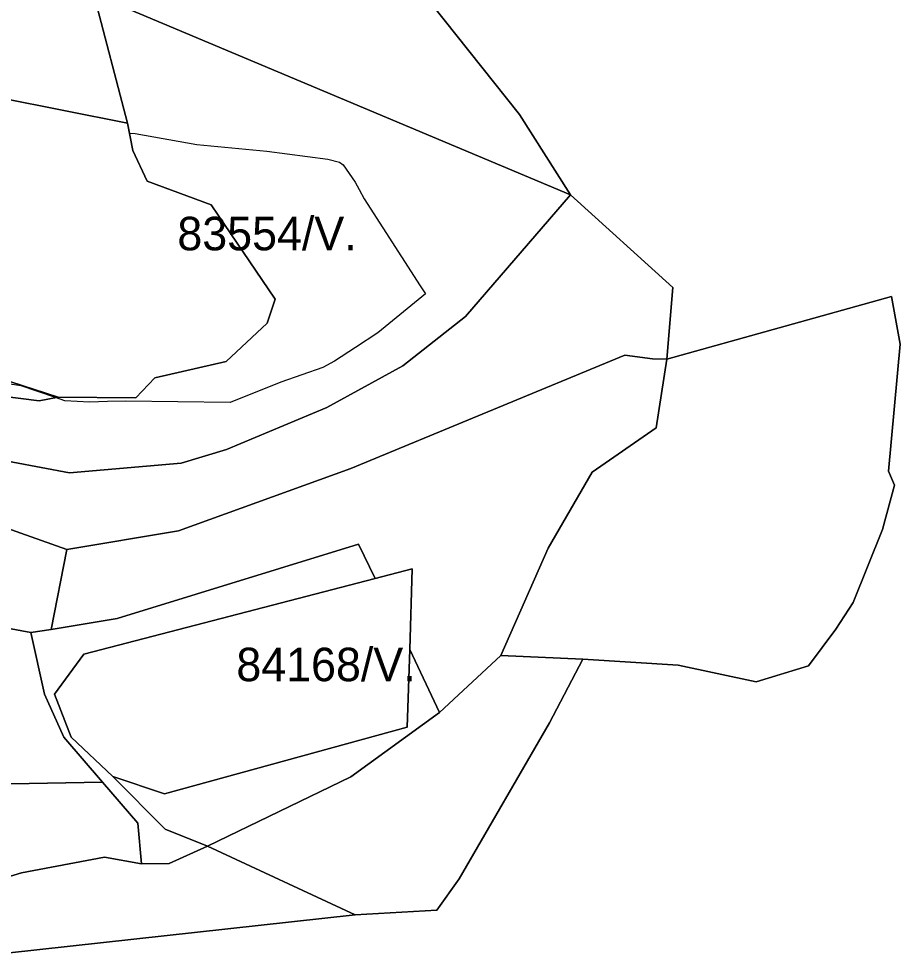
# Model space of a CAD drawing. Extents: x -477304 to -465429, y -1159113 to -1149210.
# Drawn here: x -473852.4 to -473457.6, y -1153159.5 to -1152741 of the extents above; entities that cross this region are included whole.
import ezdxf

# ---------------------------------------------------------------- set-up
doc = ezdxf.new("R2010")
doc.units = 0
for name, color, linetype in [('BPEJ_s', 7, 'Continuous'), ('PUPFL_s', 7, 'Continuous'), ('trav_porost_s', 7, 'Continuous')]:
    doc.layers.add(name, color=color, linetype=linetype)

msp = doc.modelspace()

# ---------------------------------------------------------------- linework, layer by layer
at = {"layer": 'BPEJ_s'}
for points in [[(-473860.68, -1152776.54), (-473803.74, -1152787.82), (-473802.88, -1152792.33), (-473800.3, -1152792.48), (-473772.63, -1152797.38), (-473760.04, -1152798.58), (-473741.35, -1152800.35), (-473713.91, -1152803.97), (-473708.8, -1152805.25), (-473707.1, -1152806.53), (-473701.78, -1152814.19), (-473700.01, -1152817.45), (-473697.73, -1152821.63), (-473672.63, -1152860.57), (-473670.24, -1152864.27), (-473691.56, -1152881.64), (-473701.53, -1152888.21), (-473710.93, -1152894.4), (-473716.25, -1152897.17), (-473734.97, -1152903.77), (-473757.74, -1152912.92), (-473804.55, -1152912.28), (-473812.67, -1152912.49), (-473820.72, -1152912.7), (-473831.78, -1152912.06), (-473835.95, -1152910.66), (-473851.36, -1152905.47), (-473856.47, -1152904.62)], [(-473860.68, -1152776.54), (-473803.74, -1152787.82), (-473802.88, -1152792.33), (-473800.3, -1152792.48), (-473772.63, -1152797.38), (-473760.04, -1152798.58), (-473741.35, -1152800.35), (-473713.91, -1152803.97), (-473708.8, -1152805.25), (-473707.1, -1152806.53), (-473701.78, -1152814.19), (-473700.01, -1152817.45), (-473697.73, -1152821.63), (-473672.63, -1152860.57), (-473670.24, -1152864.27), (-473691.56, -1152881.64), (-473701.53, -1152888.21), (-473710.93, -1152894.4), (-473716.25, -1152897.17), (-473734.97, -1152903.77), (-473757.74, -1152912.92), (-473804.55, -1152912.28), (-473812.67, -1152912.49), (-473820.72, -1152912.7), (-473831.78, -1152912.06), (-473835.95, -1152910.66), (-473851.36, -1152905.47), (-473856.47, -1152904.62)], [(-473677.19, -1153023.46), (-473678.51, -1153058.19), (-473787.15, -1153088.01), (-473810.27, -1153080.25), (-473828.87, -1153062.69), (-473836.45, -1153043.48), (-473823.31, -1153025.6), (-473692.78, -1152991.62), (-473676.17, -1152987.29), (-473677.19, -1153023.46)]]:
    msp.add_lwpolyline(points, dxfattribs=at)
msp.add_lwpolyline([(-473678.51, -1153058.19), (-473787.15, -1153088.01), (-473810.27, -1153080.25), (-473828.87, -1153062.69), (-473836.45, -1153043.48), (-473823.31, -1153025.6), (-473692.78, -1152991.62), (-473676.17, -1152987.29), (-473677.19, -1153023.46)], close=True, dxfattribs=at)
at = {"layer": 'PUPFL_s'}
for points in [[(-473869.86, -1152675.74), (-473854.44, -1152610.53), (-473844.11, -1152615.69), (-473806.25, -1152626.1), (-473785.42, -1152640.23), (-473773.81, -1152648.75), (-473720.65, -1152687.75), (-473718.59, -1152689.27), (-473689.18, -1152710.85), (-473681.31, -1152718.42), (-473667.69, -1152734.2), (-473628.1, -1152783.99), (-473605.28, -1152819.93), (-473818.76, -1152730.12), (-473866.02, -1152692.05)], [(-473605.28, -1152819.93), (-473559.4, -1152861.38), (-473562.2, -1152893.41), (-473568.51, -1152893.26), (-473580.94, -1152891.7), (-473703.65, -1152942.41), (-473780.92, -1152970.39), (-473830.88, -1152978.61), (-473858.21, -1152968.94), (-473932.87, -1152939.58), (-473931.31, -1152925.22), (-473829.65, -1152944.31), (-473779.71, -1152940.02), (-473759.33, -1152933.96), (-473714.49, -1152915.07), (-473680.41, -1152896.49), (-473652.27, -1152874.34)], [(-473636.51, -1153026.2), (-473615.22, -1152978.15), (-473595.64, -1152944.05), (-473566.85, -1152924.27), (-473562.2, -1152893.41), (-473461.58, -1152865.37), (-473457.56, -1152886.8), (-473462.87, -1152943.67), (-473460.13, -1152949.8), (-473465.6, -1152969.78), (-473478.61, -1153002.33), (-473486.49, -1153014.41), (-473498.71, -1153030.69), (-473522.18, -1153037.94), (-473557.06, -1153030.52), (-473599.81, -1153027.7)], [(-473843.32, -1152912.12), (-473875.09, -1152908.03), (-473902.48, -1152910.74), (-473948.56, -1152907.91), (-473962.68, -1152914.6), (-473964.53, -1152910.42), (-473951.84, -1152902.09), (-473947.37, -1152895.8), (-473928.69, -1152905.66), (-473922.23, -1152891.44), (-473904.07, -1152888.15), (-473834.72, -1152910.42)], [(-473663.99, -1153051.68), (-473677.19, -1153023.46), (-473676.17, -1152987.29), (-473692.78, -1152991.62), (-473700.17, -1152976.27), (-473808.35, -1153009.59), (-473837.96, -1153014.54), (-473830.88, -1152978.61), (-473780.92, -1152970.39), (-473703.65, -1152942.41), (-473580.94, -1152891.7), (-473568.51, -1152893.26), (-473562.2, -1152893.41), (-473566.85, -1152924.27), (-473595.64, -1152944.05), (-473615.22, -1152978.15), (-473636.51, -1153026.2)], [(-473941.25, -1152960.21), (-473960.61, -1152963.03), (-473932.87, -1152939.58), (-473858.21, -1152968.94), (-473830.88, -1152978.61), (-473837.96, -1153014.54), (-473846.96, -1153015.83), (-473896.11, -1153006.76), (-473901.36, -1153006.1), (-473923.74, -1152985.01)], [(-473810.27, -1153080.25), (-473786.86, -1153103.88), (-473767.89, -1153111.54), (-473785.09, -1153119.27), (-473797.46, -1153119.43), (-473799.07, -1153101.23), (-473814.86, -1153082.86), (-473832.18, -1153062.72), (-473840.86, -1153043.38), (-473846.96, -1153015.83), (-473837.96, -1153014.54), (-473808.35, -1153009.59), (-473700.17, -1152976.27), (-473692.78, -1152991.62), (-473823.31, -1153025.6), (-473836.45, -1153043.48), (-473828.87, -1153062.69)], [(-473917.16, -1153024.93), (-473896.11, -1153006.76), (-473846.96, -1153015.83), (-473840.86, -1153043.38), (-473832.18, -1153062.72), (-473814.86, -1153082.86), (-473921.91, -1153084.81), (-473923.67, -1153077.2), (-473937.86, -1153051.01)], [(-473677.19, -1153023.46), (-473663.99, -1153051.68), (-473703.72, -1153080.41), (-473767.89, -1153111.54), (-473786.86, -1153103.88), (-473810.27, -1153080.25), (-473787.15, -1153088.01), (-473678.51, -1153058.19)], [(-473636.51, -1153026.2), (-473599.81, -1153027.7), (-473614.65, -1153056.21), (-473655.22, -1153126.19), (-473665.18, -1153140.21), (-473701.66, -1153142.3), (-473767.89, -1153111.54), (-473703.72, -1153080.41), (-473663.99, -1153051.68)], [(-473767.89, -1153111.54), (-473701.66, -1153142.3), (-473857.93, -1153159.46), (-474018.65, -1153088.27), (-473937.86, -1153051.01), (-473923.67, -1153077.2), (-473921.91, -1153084.81), (-473914.73, -1153117), (-473905.05, -1153129.55), (-473886.33, -1153134.08), (-473851.22, -1153123.4), (-473814.05, -1153116.48), (-473797.46, -1153119.43), (-473785.09, -1153119.27)], [(-473914.73, -1153117), (-473921.91, -1153084.81), (-473814.86, -1153082.86), (-473799.07, -1153101.23), (-473797.46, -1153119.43), (-473814.05, -1153116.48), (-473851.22, -1153123.4), (-473886.33, -1153134.08), (-473905.05, -1153129.55)]]:
    msp.add_lwpolyline(points, close=True, dxfattribs=at)
for points in [[(-473818.76, -1152730.12), (-473803.74, -1152787.82), (-473860.68, -1152776.54), (-473874.11, -1152770.31), (-473929.43, -1152771.45), (-473932.21, -1152771.08), (-473954.47, -1152759.37), (-473977.56, -1152750.17), (-474006.13, -1152742.2), (-474034.45, -1152747.08), (-474056.1, -1152742.95), (-474111, -1152688.5)], [(-473875.09, -1152908.03), (-473843.32, -1152912.12), (-473834.72, -1152910.42), (-473799.98, -1152910.83), (-473791.42, -1152901.8), (-473759.56, -1152894.5), (-473741.13, -1152877.31), (-473737.53, -1152866.67), (-473766.25, -1152824.38), (-473794.85, -1152813.74), (-473801.39, -1152800.09), (-473803.74, -1152787.82), (-473818.76, -1152730.12), (-473605.28, -1152819.93), (-473652.27, -1152874.34), (-473680.41, -1152896.49), (-473714.49, -1152915.07), (-473759.33, -1152933.96), (-473779.71, -1152940.02), (-473829.65, -1152944.31), (-473931.31, -1152925.22)], [(-473857.93, -1153159.46), (-473701.66, -1153142.3), (-473665.18, -1153140.21), (-473655.22, -1153126.19), (-473614.65, -1153056.21), (-473599.81, -1153027.7), (-473557.06, -1153030.52), (-473522.18, -1153037.94), (-473498.71, -1153030.69), (-473486.49, -1153014.41), (-473478.61, -1153002.33), (-473465.6, -1152969.78), (-473460.13, -1152949.8), (-473462.87, -1152943.67), (-473457.56, -1152886.8), (-473461.58, -1152865.37), (-473562.2, -1152893.41), (-473559.4, -1152861.38), (-473605.28, -1152819.93), (-473628.1, -1152783.99), (-473667.69, -1152734.2)]]:
    msp.add_lwpolyline(points, dxfattribs=at)
at = {"layer": 'trav_porost_s'}
msp.add_lwpolyline([(-473860.68, -1152776.54), (-473803.74, -1152787.82), (-473801.39, -1152800.09), (-473794.85, -1152813.74), (-473766.25, -1152824.38), (-473737.53, -1152866.67), (-473741.13, -1152877.31), (-473759.56, -1152894.5), (-473791.42, -1152901.8), (-473799.98, -1152910.83), (-473834.72, -1152910.42), (-473904.07, -1152888.15)], dxfattribs=at)
msp.add_lwpolyline([(-473828.87, -1153062.69), (-473836.45, -1153043.48), (-473823.31, -1153025.6), (-473692.78, -1152991.62), (-473676.17, -1152987.29), (-473677.19, -1153023.46), (-473678.51, -1153058.19), (-473787.15, -1153088.01), (-473810.27, -1153080.25)], close=True, dxfattribs=at)

# ---------------------------------------------------------------- texts
at = {"layer": 'BPEJ_s'}
for s, p in [('83554/V.', (-473781.37, -1152844.73)), ('84168/V.', (-473754.95, -1153037.65))]:
    msp.add_text(s, height=15, dxfattribs=at).set_placement(p)

doc.saveas('drawing.dxf')
